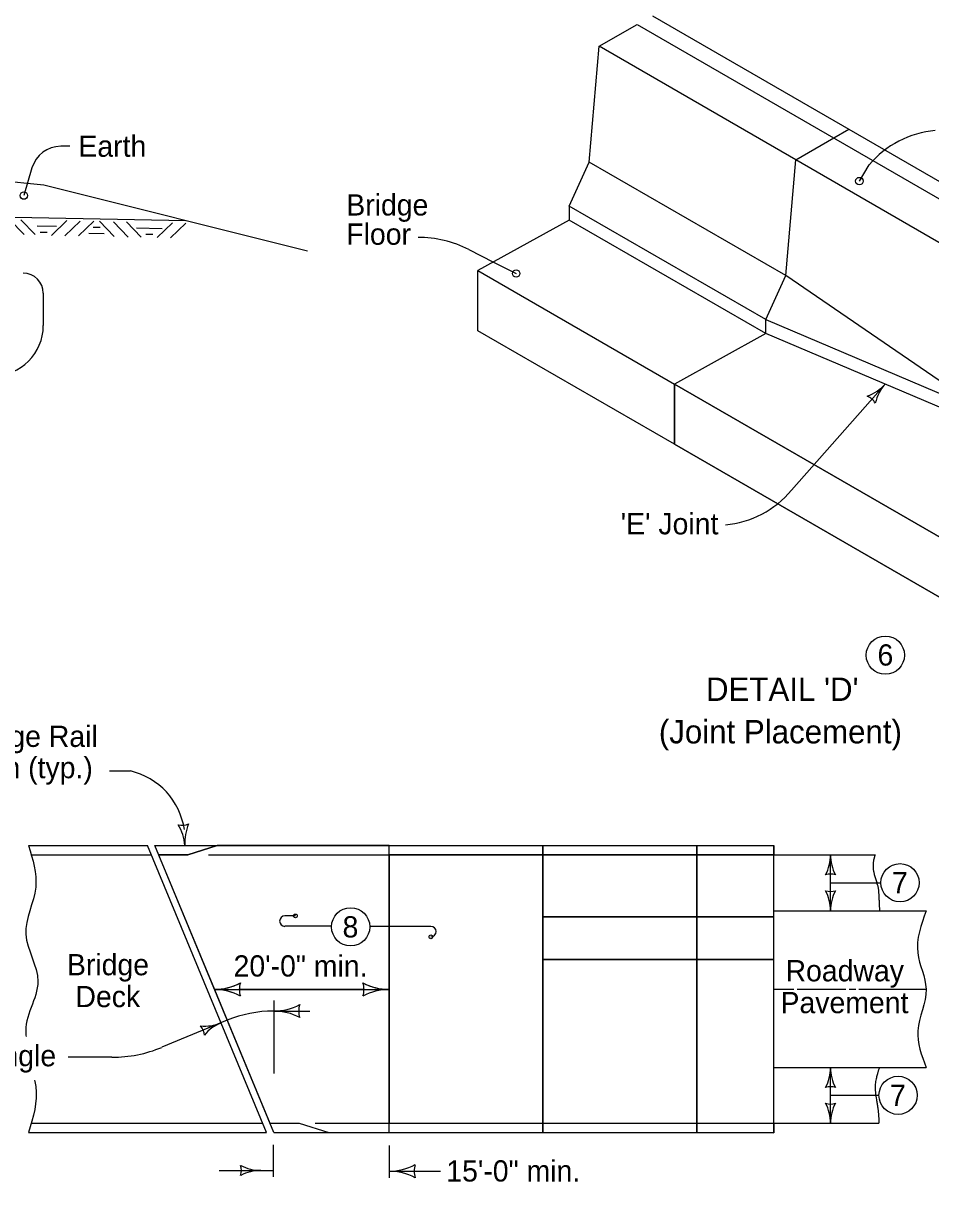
# Model space of a CAD drawing. Extents: x -2135039 to -2120895, y -2139150 to -2136566.
# Drawn here: x -2123042 to -2122188, y -2138208 to -2137117 of the extents above; entities that cross this region are included whole.
import ezdxf

# ---------------------------------------------------------------- set-up
doc = ezdxf.new("R2010")
doc.units = 0
for name, color, linetype in [('dsnCellElements', 7, 'Continuous'), ('dsnStdLabel', 7, 'Continuous'), ('Level 2', 7, 'Continuous'), ('Level 3', 7, 'Continuous')]:
    doc.layers.add(name, color=color, linetype=linetype)

msp = doc.modelspace()

# ---------------------------------------------------------------- linework, layer by layer
at = {"layer": 'dsnCellElements'}
for centre in [(-2122255.1, -2137266.1), (-2123041.8, -2137279.7), (-2122578.2, -2137353.1)]:
    msp.add_circle(centre, 3.54, dxfattribs=at)
at = {"layer": 'dsnStdLabel'}
for centre in [(-2122786.1, -2137957.9), (-2122658.5, -2137977.6)]:
    msp.add_circle(centre, 1.78, dxfattribs=at)
for centre, radius, start, end in [((-2122262.5, -2137428.8), 42.5, 290.5435, 318.616), ((-2122198.7, -2137485), 42.5, 138.616, 166.6885), ((-2122254.2, -2137483.6), 16.4, 30.8827, 66.3494), ((-2122892.8, -2137856.1), 16.4, 256.6331, 292.0998), ((-2122932.5, -2137894.8), 42.5, 4.3665, 32.439), ((-2122847.7, -2137888.4), 42.5, 156.294, 184.3665)]:
    msp.add_arc(centre, radius, start, end, dxfattribs=at)
at = {"layer": 'Level 2'}
for p, q in [((-2122450, -2137110.4), (-2121948.3, -2137400.1)), ((-2122279.2, -2137225.3), (-2122265, -2137217.2)), ((-2122998.6, -2137233.3), (-2123006.9, -2137233.3)), ((-2123034.2, -2137253.7), (-2123041.8, -2137279.7)), ((-2122324.4, -2137355.1), (-2122509.4, -2137248.3)), ((-2122255.1, -2137266.1), (-2122245.8, -2137250.8)), ((-2123135.2, -2137258.5), (-2123022.9, -2137269.7)), ((-2123022.9, -2137269.7), (-2122774.7, -2137331.8)), ((-2122343.3, -2137396.5), (-2122528.3, -2137289.7)), ((-2122528.3, -2137289.7), (-2122528.3, -2137302.8)), ((-2123067.1, -2137299.6), (-2122889.3, -2137303.1)), ((-2123055.4, -2137302.1), (-2123041.6, -2137316.5)), ((-2123044.6, -2137302.4), (-2123031.2, -2137316.4)), ((-2123001.3, -2137303.3), (-2123015.8, -2137317.2)), ((-2122988.9, -2137303.8), (-2123003.3, -2137317.6)), ((-2122975.9, -2137303.8), (-2122990.3, -2137317.7)), ((-2122970.5, -2137303.9), (-2122956.6, -2137318.3)), ((-2122957.5, -2137304.4), (-2122943.6, -2137318.8)), ((-2122945, -2137304.4), (-2122931.2, -2137318.9)), ((-2122901.8, -2137305.3), (-2122916.2, -2137319.2)), ((-2122889.4, -2137305.8), (-2122903.8, -2137319.6)), ((-2122622.9, -2137330.5), (-2122599.6, -2137342.3)), ((-2122599.6, -2137342.3), (-2122578.2, -2137353.1)), ((-2123023.5, -2137371.7), (-2123023.5, -2137402.1)), ((-2122343.3, -2137409.6), (-2122429.2, -2137457.2)), ((-2122343.3, -2137409.6), (-2122429.2, -2137457.2)), ((-2122154.6, -2137489.7), (-2122343.3, -2137409.6)), ((-2122134, -2137498.4), (-2122343.3, -2137409.6)), ((-2122429.2, -2137457.2), (-2122429.2, -2137513.8)), ((-2122175, -2137603.9), (-2122429.2, -2137457.2)), ((-2122429.2, -2137457.2), (-2122429.2, -2137513.8)), ((-2122429.2, -2137457.2), (-2122175, -2137603.9)), ((-2122429.2, -2137457.2), (-2121991.9, -2137709.6)), ((-2122230.6, -2137456.9), (-2122319, -2137557.2)), ((-2122429.2, -2137513.8), (-2121991.9, -2137766.2)), ((-2122429.2, -2137513.8), (-2122157.2, -2137670.8)), ((-2121991.9, -2137766.2), (-2122429.2, -2137513.8)), ((-2122941.4, -2137821.5), (-2122961, -2137821.5)), ((-2123037.5, -2137891.6), (-2122925.2, -2137891.6)), ((-2122813.2, -2138161.9), (-2122925.2, -2137891.6)), ((-2122806.5, -2138161.9), (-2122918.5, -2137891.6)), ((-2122918.5, -2137891.6), (-2122697.9, -2137891.6)), ((-2122887.5, -2137900.3), (-2122859.8, -2137891.6)), ((-2122697.9, -2137953), (-2122697.9, -2137891.6)), ((-2122697.9, -2138153.1), (-2122697.9, -2137891.6)), ((-2122697.9, -2137891.6), (-2122335.6, -2137891.7)), ((-2122553, -2138162), (-2122553, -2137891.6)), ((-2122408, -2138162), (-2122408, -2137891.6)), ((-2122335.6, -2138162), (-2122335.6, -2137891.7)), ((-2123034.6, -2137900.3), (-2122921.6, -2137900.3)), ((-2122914.9, -2137900.3), (-2122887.5, -2137900.3)), ((-2122867.9, -2137900.3), (-2122240.3, -2137900.3)), ((-2122553, -2137900.3), (-2122697.9, -2137900.3)), ((-2122335.6, -2138153.1), (-2122335.6, -2137900.3)), ((-2122282.2, -2137953.1), (-2122282.2, -2137900.3)), ((-2122282.2, -2137926.7), (-2122252.8, -2137926.7)), ((-2122252.8, -2137926.7), (-2122234.8, -2137926.7)), ((-2122335.6, -2137953.1), (-2122192.3, -2137953.1)), ((-2122786.1, -2137957.9), (-2122796, -2137957.9)), ((-2122752.1, -2137967.7), (-2122796, -2137967.7)), ((-2122716.1, -2137967.7), (-2122658.5, -2137967.7)), ((-2122862.5, -2138027.1), (-2122697.9, -2138027.1)), ((-2122721.5, -2138027.1), (-2122838.9, -2138027.1)), ((-2122838.9, -2138027.1), (-2122721.5, -2138027.1)), ((-2122697.9, -2138027.1), (-2122697.9, -2138027.1)), ((-2122697.9, -2138027.1), (-2122697.9, -2138095.1)), ((-2122806.5, -2138037.5), (-2122806.5, -2138106.2)), ((-2122806.5, -2138047.5), (-2122772.6, -2138047.5)), ((-2122850.4, -2138056.2), (-2122911.7, -2138081.6)), ((-2122958.8, -2138091), (-2123000.2, -2138091)), ((-2122697.9, -2138095.1), (-2122697.9, -2138153.1)), ((-2122697.9, -2138161.9), (-2122697.9, -2138095.1)), ((-2122335.6, -2138100.6), (-2122192.3, -2138100.6)), ((-2122282.2, -2138153.1), (-2122282.2, -2138100.6)), ((-2122282.2, -2138126.8), (-2122252.8, -2138126.8)), ((-2122252.8, -2138126.8), (-2122236.6, -2138126.8)), ((-2123034.8, -2138153.1), (-2122816.9, -2138153.1)), ((-2122810.2, -2138153.1), (-2122782.7, -2138153.1)), ((-2122810.2, -2138153.1), (-2122782.7, -2138153.1)), ((-2122782.7, -2138153.1), (-2122754.5, -2138161.9)), ((-2122782.7, -2138153.1), (-2122754.5, -2138161.9)), ((-2122767.5, -2138153.1), (-2122236.6, -2138153.1)), ((-2122697.9, -2138153.1), (-2122647.4, -2138153.1)), ((-2122647.4, -2138153.1), (-2122647.4, -2138153.1)), ((-2123037.5, -2138161.9), (-2122813.2, -2138161.9)), ((-2122806.5, -2138161.9), (-2122697.9, -2138161.9)), ((-2122754.5, -2138161.9), (-2122697.9, -2138161.9)), ((-2122697.9, -2138161.9), (-2122335.6, -2138162)), ((-2122806.9, -2138173.5), (-2122806.9, -2138203.7)), ((-2122697.9, -2138174.2), (-2122697.9, -2138204.4)), ((-2122857.9, -2138197.5), (-2122806.9, -2138197.5)), ((-2122697.9, -2138198.2), (-2122649.5, -2138198.2))]:
    msp.add_line(p, q, dxfattribs=at)
for points in [[(-2122464.2, -2137118.5), (-2122098.2, -2137329.8), (-2122007.7, -2137382.1), (-2121962.4, -2137408.2), (-2121990.7, -2137424.6), (-2122043.5, -2137402.8), (-2122134, -2137350.5), (-2122315, -2137246), (-2122500, -2137139.2)], [(-2122500, -2137139.2), (-2122464.2, -2137118.5)], [(-2122528.3, -2137289.7), (-2122509.4, -2137248.3), (-2122500, -2137139.2)], [(-2122315, -2137246), (-2122279.2, -2137225.3)], [(-2122343.3, -2137409.6), (-2122343.3, -2137396.5), (-2122324.4, -2137355.1), (-2122315, -2137246)], [(-2123029.1, -2137308.2), (-2123011, -2137308.6)], [(-2122976.6, -2137309.3), (-2122970, -2137309.4)], [(-2122528.3, -2137302.8), (-2122614.2, -2137350.4)], [(-2122343.3, -2137409.6), (-2122528.3, -2137302.8)], [(-2123026.4, -2137314.1), (-2123019.9, -2137314.2)], [(-2122980.5, -2137315.1), (-2122966.3, -2137315.4)], [(-2122935.6, -2137310.1), (-2122911.5, -2137310.6)], [(-2122926.9, -2137316.1), (-2122920.4, -2137316.2)], [(-2122614.2, -2137350.4), (-2122429.2, -2137457.2)], [(-2122614.2, -2137407), (-2122614.2, -2137350.4)], [(-2122343.3, -2137396.5), (-2122134, -2137485.3), (-2122324.4, -2137355.1)], [(-2122429.2, -2137513.8), (-2122614.2, -2137407)], [(-2122343.3, -2137409.6), (-2122429.2, -2137457.2)], [(-2122429.2, -2137513.8), (-2122429.2, -2137457.2)], [(-2122698.6, -2138027.1), (-2122697.9, -2138027.1), (-2122697.9, -2137891.6), (-2122859.8, -2137891.6), (-2122887.5, -2137900.3), (-2122914.9, -2137900.3), (-2122862.4, -2138027.1), (-2122861.8, -2138027.1)], [(-2122697.9, -2137900.3), (-2122697.9, -2137967.7), (-2122697.9, -2138027.1)], [(-2122553, -2138153.1), (-2122553, -2138026.7), (-2122553, -2137900.3)], [(-2122862.4, -2138027.1), (-2122850.3, -2138056.2), (-2122810.2, -2138153.1)], [(-2122697.9, -2138161.9), (-2122697.9, -2138153.1), (-2122697.9, -2138100.5), (-2122697.9, -2138027.1)], [(-2122697.9, -2138027.1), (-2122697.9, -2138027.1)], [(-2122335.6, -2138026.8), (-2122316.9, -2138026.8)], [(-2122313.8, -2138026.8), (-2122267.7, -2138026.8)], [(-2122264.7, -2138026.8), (-2122258.5, -2138026.8)], [(-2122255.5, -2138026.8), (-2122192.3, -2138026.8)], [(-2122647.4, -2138153.1), (-2122599.7, -2138153.1), (-2122553, -2138153.1)]]:
    msp.add_lwpolyline(points, dxfattribs=at)
for centre in [(-2122230.6, -2137712.4), (-2122216.8, -2137926.7), (-2122734.1, -2137968.2), (-2122218.6, -2138126.8)]:
    msp.add_circle(centre, 18, dxfattribs=at)
for centre, radius, start, end in [((-2122175.9, -2137309.2), 91, 94.8409, 140.1467), ((-2123006.9, -2137261.7), 28.4, 90, 163.739), ((-2122670.6, -2137425), 105.9, 63.2177, 90), ((-2123042.4, -2137371.7), 18.9, 0, 90), ((-2123070.8, -2137402.1), 47.3, 270, 360), ((-2122388.9, -2137498.9), 91, 274.8409, 320.1467), ((-2122956.6, -2137886.4), 66.7, 8.4828, 76.8823), ((-2122322.4, -2137900.3), 40.2, 331.9275, 360), ((-2122242.1, -2137900.3), 40.2, 180, 208.0725), ((-2122282.2, -2137934), 15.5, 72.2666, 107.7334), ((-2122282.2, -2137919.4), 15.5, 252.2666, 287.7333), ((-2122322.4, -2137953.1), 40.2, 360, 28.0725), ((-2122242.1, -2137953.1), 40.2, 151.9275, 180), ((-2122796, -2137962.8), 4.92, 90, 270), ((-2122658.5, -2137972.7), 4.92, 270, 90), ((-2122862.5, -2137974.9), 52.2, 270, 298.0725), ((-2122862.5, -2138079.4), 52.2, 61.9275, 90), ((-2122862.5, -2138079.4), 52.2, 61.9275, 89.8364), ((-2122862.5, -2137974.9), 52.2, 270.8433, 298.0725), ((-2122818.7, -2138027.1), 20.2, 162.2666, 197.7334), ((-2122818.7, -2138027.1), 20.2, 162.2667, 179.9839), ((-2122818.7, -2138027.1), 20.2, 179.9839, 197.7334), ((-2122741.7, -2138027.1), 20.2, 342.2666, 17.7334), ((-2122697.9, -2137974.9), 52.2, 241.9275, 270), ((-2122741.7, -2138027.1), 20.2, 0.0161, 17.7334), ((-2122697.9, -2137974.9), 52.2, 241.9275, 269.1567), ((-2122697.9, -2138079.4), 52.2, 90.0176, 118.0725), ((-2122741.7, -2138027.1), 20.2, 342.2666, 0.0161), ((-2122697.9, -2138079.4), 52.2, 90, 118.0725), ((-2122697.9, -2137974.9), 52.2, 269.9824, 270), ((-2122806.6, -2138162), 114.5, 90, 112.5), ((-2122806.5, -2137995.3), 52.2, 270, 298.0725), ((-2122806.5, -2137995.3), 52.2, 270, 298.0725), ((-2122806.5, -2138099.7), 52.2, 61.9275, 90), ((-2122806.5, -2138099.7), 52.2, 61.9275, 90), ((-2122762.8, -2138047.5), 20.2, 162.2666, 197.7334), ((-2122762.8, -2138047.5), 20.2, 162.2666, 197.7334), ((-2122871.4, -2138021.5), 40.2, 264.4275, 292.5), ((-2122887.2, -2138071.5), 15.5, 4.7666, 40.2333), ((-2122840.7, -2138095.7), 40.2, 112.5, 140.5725), ((-2122958.8, -2137968.1), 122.9, 270, 292.5), ((-2122322.4, -2138100.6), 40.2, 331.9275, 360), ((-2122242.1, -2138100.6), 40.2, 180, 208.0725), ((-2122282.2, -2138134.2), 15.5, 72.2666, 107.7334), ((-2122282.2, -2138119.5), 15.5, 252.2666, 287.7333), ((-2122322.4, -2138153.1), 40.2, 360, 28.0725), ((-2122242.1, -2138153.1), 40.2, 151.9275, 180), ((-2122687.6, -2138153.1), 40.2, 359.9859, 360), ((-2122852.4, -2138197.5), 15.5, 342.2666, 17.7334), ((-2122818.7, -2138157.3), 40.2, 241.9275, 270), ((-2122697.9, -2138146), 52.2, 270, 298.0725), ((-2122654.1, -2138198.3), 20.2, 162.2666, 197.7334), ((-2122818.7, -2138237.7), 40.2, 90, 118.0725), ((-2122697.9, -2138250.5), 52.2, 61.9275, 90)]:
    msp.add_arc(centre, radius, start, end, dxfattribs=at)
for points in [[(-2123037.5, -2137891.6), (-2123030.6, -2137930.8), (-2123039.9, -2137975.2), (-2123028.6, -2138019.5), (-2123039.9, -2138069.1), (-2123039.6, -2138071.4)], [(-2122192.3, -2137953.1), (-2122200.1, -2137992.8), (-2122192.3, -2138026.9), (-2122200.1, -2138066), (-2122192.3, -2138100.6)], [(-2123031.8, -2138112.4), (-2123030.6, -2138118.6), (-2123037.5, -2138161.9)]]:
    msp.add_spline(points, degree=3, dxfattribs=at)
for points in [[(-2122240.3, -2137900.3), (-2122240.4, -2137900.8), (-2122240.6, -2137901.3), (-2122240.8, -2137901.8), (-2122240.9, -2137902.3), (-2122241, -2137902.8), (-2122241.2, -2137903.3), (-2122241.4, -2137904.3), (-2122241.7, -2137905.2), (-2122241.8, -2137906.3), (-2122242, -2137907.2), (-2122242.1, -2137908.2), (-2122242.2, -2137909.2), (-2122242.2, -2137909.7), (-2122242.2, -2137910.2), (-2122242.2, -2137910.7), (-2122242.2, -2137911.2), (-2122242.2, -2137911.7), (-2122242.2, -2137912.2), (-2122242.1, -2137913.2), (-2122242, -2137914.1), (-2122241.9, -2137915.1), (-2122241.7, -2137916), (-2122241.5, -2137917), (-2122241.3, -2137917.9), (-2122240.7, -2137919.8), (-2122240.1, -2137921.6), (-2122239.6, -2137923.5), (-2122239, -2137925.4), (-2122238.5, -2137927.3), (-2122237.9, -2137929.2), (-2122237.7, -2137930.1), (-2122237.5, -2137931.1), (-2122237.3, -2137932.1), (-2122237.2, -2137933), (-2122237.1, -2137934), (-2122237, -2137934.9), (-2122236.9, -2137936.5), (-2122236.9, -2137938), (-2122236.8, -2137939.5), (-2122236.7, -2137941), (-2122236.6, -2137942.5), (-2122236.5, -2137944), (-2122236.5, -2137945.5), (-2122236.4, -2137947), (-2122236.3, -2137948.5), (-2122236.3, -2137950), (-2122236.2, -2137951.5), (-2122236.2, -2137953.1)], [(-2122236.2, -2138100.6), (-2122236.5, -2138101.4), (-2122236.8, -2138102.3), (-2122237.1, -2138103.2), (-2122237.4, -2138104.1), (-2122237.6, -2138104.9), (-2122237.9, -2138105.8), (-2122238.4, -2138107.6), (-2122238.9, -2138109.3), (-2122239.2, -2138111.1), (-2122239.8, -2138113.7), (-2122240.1, -2138116.4), (-2122240.2, -2138119), (-2122240.2, -2138119.5), (-2122240.2, -2138119.9), (-2122240.2, -2138120.4), (-2122240.2, -2138120.8), (-2122240.1, -2138121.3), (-2122240.1, -2138121.7), (-2122240.1, -2138122.7), (-2122240, -2138123.7), (-2122239.9, -2138124.7), (-2122239.8, -2138125.7), (-2122239.7, -2138126.7), (-2122239.5, -2138127.6), (-2122239.2, -2138129.6), (-2122238.9, -2138131.6), (-2122238.6, -2138133.6), (-2122238.2, -2138135.5), (-2122237.9, -2138137.5), (-2122237.6, -2138139.5), (-2122237.5, -2138140.5), (-2122237.4, -2138141.5), (-2122237.3, -2138142.5), (-2122237.2, -2138143.5), (-2122237.1, -2138144.4), (-2122237, -2138145.4), (-2122236.9, -2138148), (-2122236.7, -2138150.6), (-2122236.6, -2138153.1)]]:
    msp.add_open_spline(points, degree=3, dxfattribs=at)
at = {"layer": 'Level 3'}
for p, q in [((-2122408, -2137900.3), (-2122553, -2137900.3)), ((-2122553, -2137900.3), (-2122553, -2137958.9)), ((-2122408, -2137958.9), (-2122408, -2137900.3)), ((-2122335.6, -2137900.3), (-2122408, -2137900.3)), ((-2122408, -2137900.3), (-2122408, -2137958.9)), ((-2122335.6, -2137958.9), (-2122335.6, -2137900.3)), ((-2122408, -2137958.9), (-2122553, -2137958.9)), ((-2122553, -2137958.9), (-2122553, -2137998.9)), ((-2122553, -2137958.9), (-2122408, -2137958.9)), ((-2122408, -2137998.9), (-2122408, -2137958.9)), ((-2122408, -2137958.9), (-2122408, -2137958.9)), ((-2122335.6, -2137958.9), (-2122408, -2137958.9)), ((-2122408, -2137958.9), (-2122408, -2137998.9)), ((-2122408, -2137958.9), (-2122335.6, -2137958.9)), ((-2122335.6, -2137998.9), (-2122335.6, -2137958.9)), ((-2122553, -2137998.9), (-2122553, -2138153.1)), ((-2122553, -2137998.9), (-2122408, -2137998.9)), ((-2122408, -2138153.1), (-2122408, -2137998.9)), ((-2122408, -2137998.9), (-2122408, -2138153.1)), ((-2122335.6, -2137998.9), (-2122408, -2137998.9)), ((-2122408, -2137998.9), (-2122335.6, -2137998.9)), ((-2122335.6, -2138153.1), (-2122335.6, -2137998.9)), ((-2122553, -2138153.1), (-2122408, -2138153.1)), ((-2122408, -2138153.1), (-2122335.6, -2138153.1))]:
    msp.add_line(p, q, dxfattribs=at)
for points in [[(-2122697.9, -2137891.6), (-2122553, -2137891.6), (-2122553, -2137900.3), (-2122672.9, -2137900.3), (-2122697.9, -2137900.3)], [(-2122408, -2137891.6), (-2122408, -2137900.3), (-2122553, -2137900.3), (-2122553, -2137891.6)], [(-2122335.6, -2137891.7), (-2122335.6, -2137900.3), (-2122408, -2137900.3), (-2122408, -2137891.6)], [(-2122553, -2138162), (-2122697.9, -2138161.9), (-2122697.9, -2138153.1), (-2122690.6, -2138153.1), (-2122647.4, -2138153.1), (-2122599.7, -2138153.1), (-2122553, -2138153.1)], [(-2122553, -2138162), (-2122553, -2138153.1), (-2122408, -2138153.1), (-2122408, -2138162)], [(-2122335.6, -2138162), (-2122408, -2138162), (-2122408, -2138153.1), (-2122335.6, -2138153.1)]]:
    msp.add_lwpolyline(points, close=True, dxfattribs=at)
msp.add_lwpolyline([(-2122408, -2137998.9), (-2122408, -2137998.9), (-2122553, -2137998.9)], dxfattribs=at)

# ---------------------------------------------------------------- texts
at = {"layer": 'Level 2'}
for s, height, p in [('Bridge', 20, (-2122738.2, -2137298.5)), ('Floor', 20, (-2122738.2, -2137326)), ("'E' Joint", 20, (-2122479.8, -2137598.7)), ("DETAIL 'D'", 22, (-2122399.5, -2137755.5)), ('Bridge Rail', 20, (-2123103, -2137798.8)), ('End Section (typ.)', 20, (-2123189.4, -2137828.3))]:
    msp.add_text(s, height=height, dxfattribs=at).set_placement(p)
at = {"layer": 'Level 3'}
for s, height, p in [('Earth', 20, (-2122990.4, -2137243.2)), ('6', 20, (-2122238, -2137722.2)), ('(Joint Placement)', 22, (-2122443.9, -2137795.5)), ('7', 20, (-2122224.4, -2137936.7)), ('8', 20, (-2122741.7, -2137978.2)), ('Bridge', 20, (-2123001.2, -2138013.8)), ('20\'-0" min.', 20, (-2122844.3, -2138015)), ('Roadway', 20, (-2122324.6, -2138019.5)), ('Deck', 20, (-2122993.2, -2138043.8)), ('Pavement', 20, (-2122329.3, -2138049.5)), ('Skew Angle', 20, (-2123152.6, -2138099.5)), ('7', 20, (-2122226.2, -2138136.8)), ('15\'-0" min.', 20, (-2122644, -2138208))]:
    msp.add_text(s, height=height, dxfattribs=at).set_placement(p)

doc.saveas('drawing.dxf')
